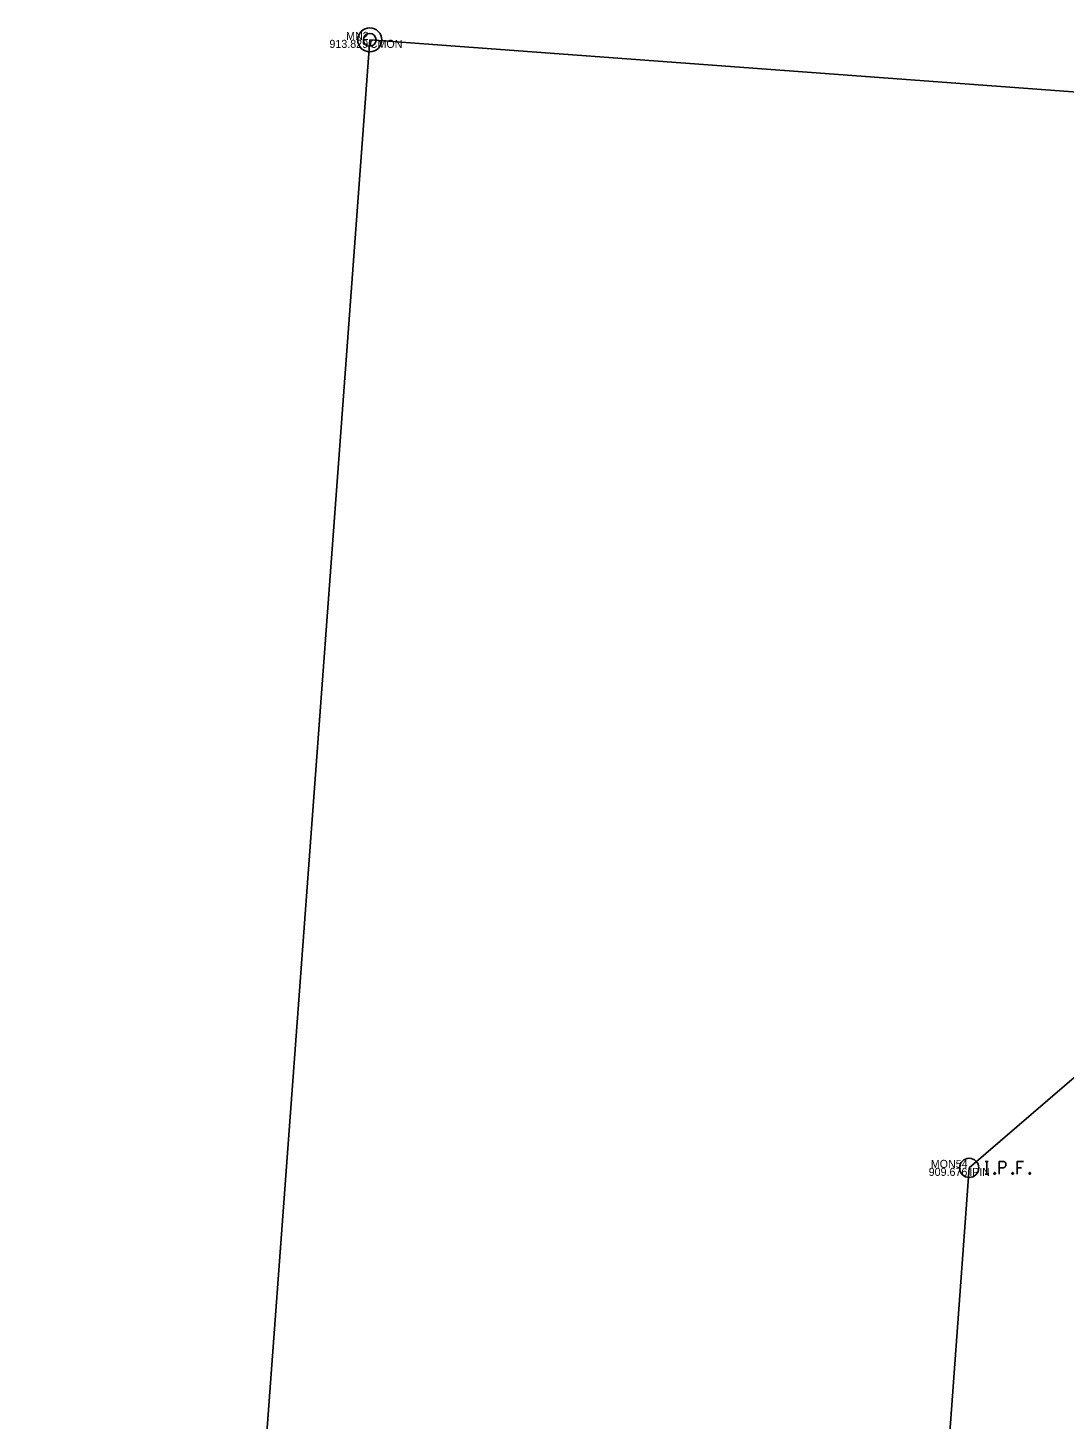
# Model space of a CAD drawing. Extents: x 1981066 to 1984208, y 708139 to 709503.
# Drawn here: x 1982456.6 to 1982586.1, y 708660.8 to 708834.6 of the extents above; entities that cross this region are included whole.
import ezdxf

# ---------------------------------------------------------------- set-up
doc = ezdxf.new("R2010")
doc.units = 0
for name, color, linetype in [('DR_X_Ditch', 7, 'Continuous'), ('DR_X_Elev_Flow', 7, 'Continuous'), ('LT_X_Poles', 7, 'Continuous'), ('SV_X_Shot_Marker', 7, 'Continuous'), ('SV_X_Toe_of_Slope', 7, 'Continuous'), ('UT_X_Misc_Cells', 7, 'Continuous')]:
    doc.layers.add(name, color=color, linetype=linetype)

msp = doc.modelspace()

# ---------------------------------------------------------------- linework, layer by layer
at = {"layer": 'DR_X_Ditch'}
for p, q in [((1982456.59, 708254.7), (1982499.31, 708833.12)), ((1982499.31, 708833.12), (1983707.34, 708743.91))]:
    msp.add_line(p, q, dxfattribs=at)
at = {"layer": 'SV_X_Shot_Marker'}
for points in [[(1982576.21, 708693.01), (1982576.57, 708693.01)], [(1982576.39, 708691.41), (1982576.39, 708693.01)], [(1982577.96, 708691.41), (1982577.96, 708693.01), (1982578.49, 708693.01), (1982578.54, 708693), (1982578.62, 708692.97), (1982578.65, 708692.94), (1982578.68, 708692.92), (1982578.73, 708692.86), (1982578.76, 708692.79), (1982578.78, 708692.69), (1982578.78, 708692.54), (1982578.77, 708692.49), (1982578.75, 708692.42), (1982578.71, 708692.33), (1982578.66, 708692.29), (1982578.63, 708692.26), (1982578.57, 708692.24), (1982578.49, 708692.23), (1982577.96, 708692.23)], [(1982580.97, 708693.01), (1982580.2, 708693.01), (1982580.2, 708691.41)], [(1982580.2, 708692.23), (1982580.74, 708692.23)], [(1982576.21, 708691.41), (1982576.57, 708691.41)], [(1982577.35, 708691.62), (1982577.4, 708691.62), (1982577.44, 708691.6), (1982577.47, 708691.55), (1982577.47, 708691.48), (1982577.44, 708691.43), (1982577.4, 708691.41), (1982577.35, 708691.41), (1982577.32, 708691.43), (1982577.28, 708691.48), (1982577.28, 708691.55), (1982577.32, 708691.6), (1982577.35, 708691.62)], [(1982579.6, 708691.62), (1982579.65, 708691.62), (1982579.69, 708691.6), (1982579.72, 708691.55), (1982579.72, 708691.48), (1982579.69, 708691.43), (1982579.65, 708691.41), (1982579.6, 708691.41), (1982579.57, 708691.43), (1982579.53, 708691.48), (1982579.53, 708691.55), (1982579.57, 708691.6), (1982579.6, 708691.62)], [(1982581.75, 708691.62), (1982581.8, 708691.62), (1982581.84, 708691.6), (1982581.87, 708691.55), (1982581.87, 708691.48), (1982581.84, 708691.43), (1982581.8, 708691.41), (1982581.75, 708691.41), (1982581.71, 708691.43), (1982581.68, 708691.48), (1982581.68, 708691.55), (1982581.71, 708691.6), (1982581.75, 708691.62)]]:
    msp.add_lwpolyline(points, dxfattribs=at)
for centre, radius in [((1982499.31, 708833.12), 1.5), ((1982499.31, 708833.12), 0.8), ((1982574.2, 708692.21), 1.2)]:
    msp.add_circle(centre, radius, dxfattribs=at)
at = {"layer": 'SV_X_Toe_of_Slope'}
for p, q in [((1982574.2, 708692.21), (1982638.45, 708747.66)), ((1982533.99, 708143.14), (1982574.2, 708692.21))]:
    msp.add_line(p, q, dxfattribs=at)

# ---------------------------------------------------------------- texts
at = {"layer": 'DR_X_Elev_Flow'}
for s, p in [('913.829', (1982494.27, 708832.12)), ('909.676', (1982569.14, 708691.21))]:
    msp.add_text(s, height=1, dxfattribs=at).set_placement(p)
at = {"layer": 'LT_X_Poles'}
for s, p in [('CMON', (1982499.31, 708832.12)), ('IPIN', (1982574.2, 708691.21))]:
    msp.add_text(s, height=1, dxfattribs=at).set_placement(p)
at = {"layer": 'UT_X_Misc_Cells'}
for s, p in [('MN2', (1982496.35, 708833.12)), ('MON54', (1982569.4, 708692.21))]:
    msp.add_text(s, height=1, dxfattribs=at).set_placement(p)

doc.saveas('drawing.dxf')
